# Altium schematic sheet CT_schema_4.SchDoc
size 293 x 258 mm
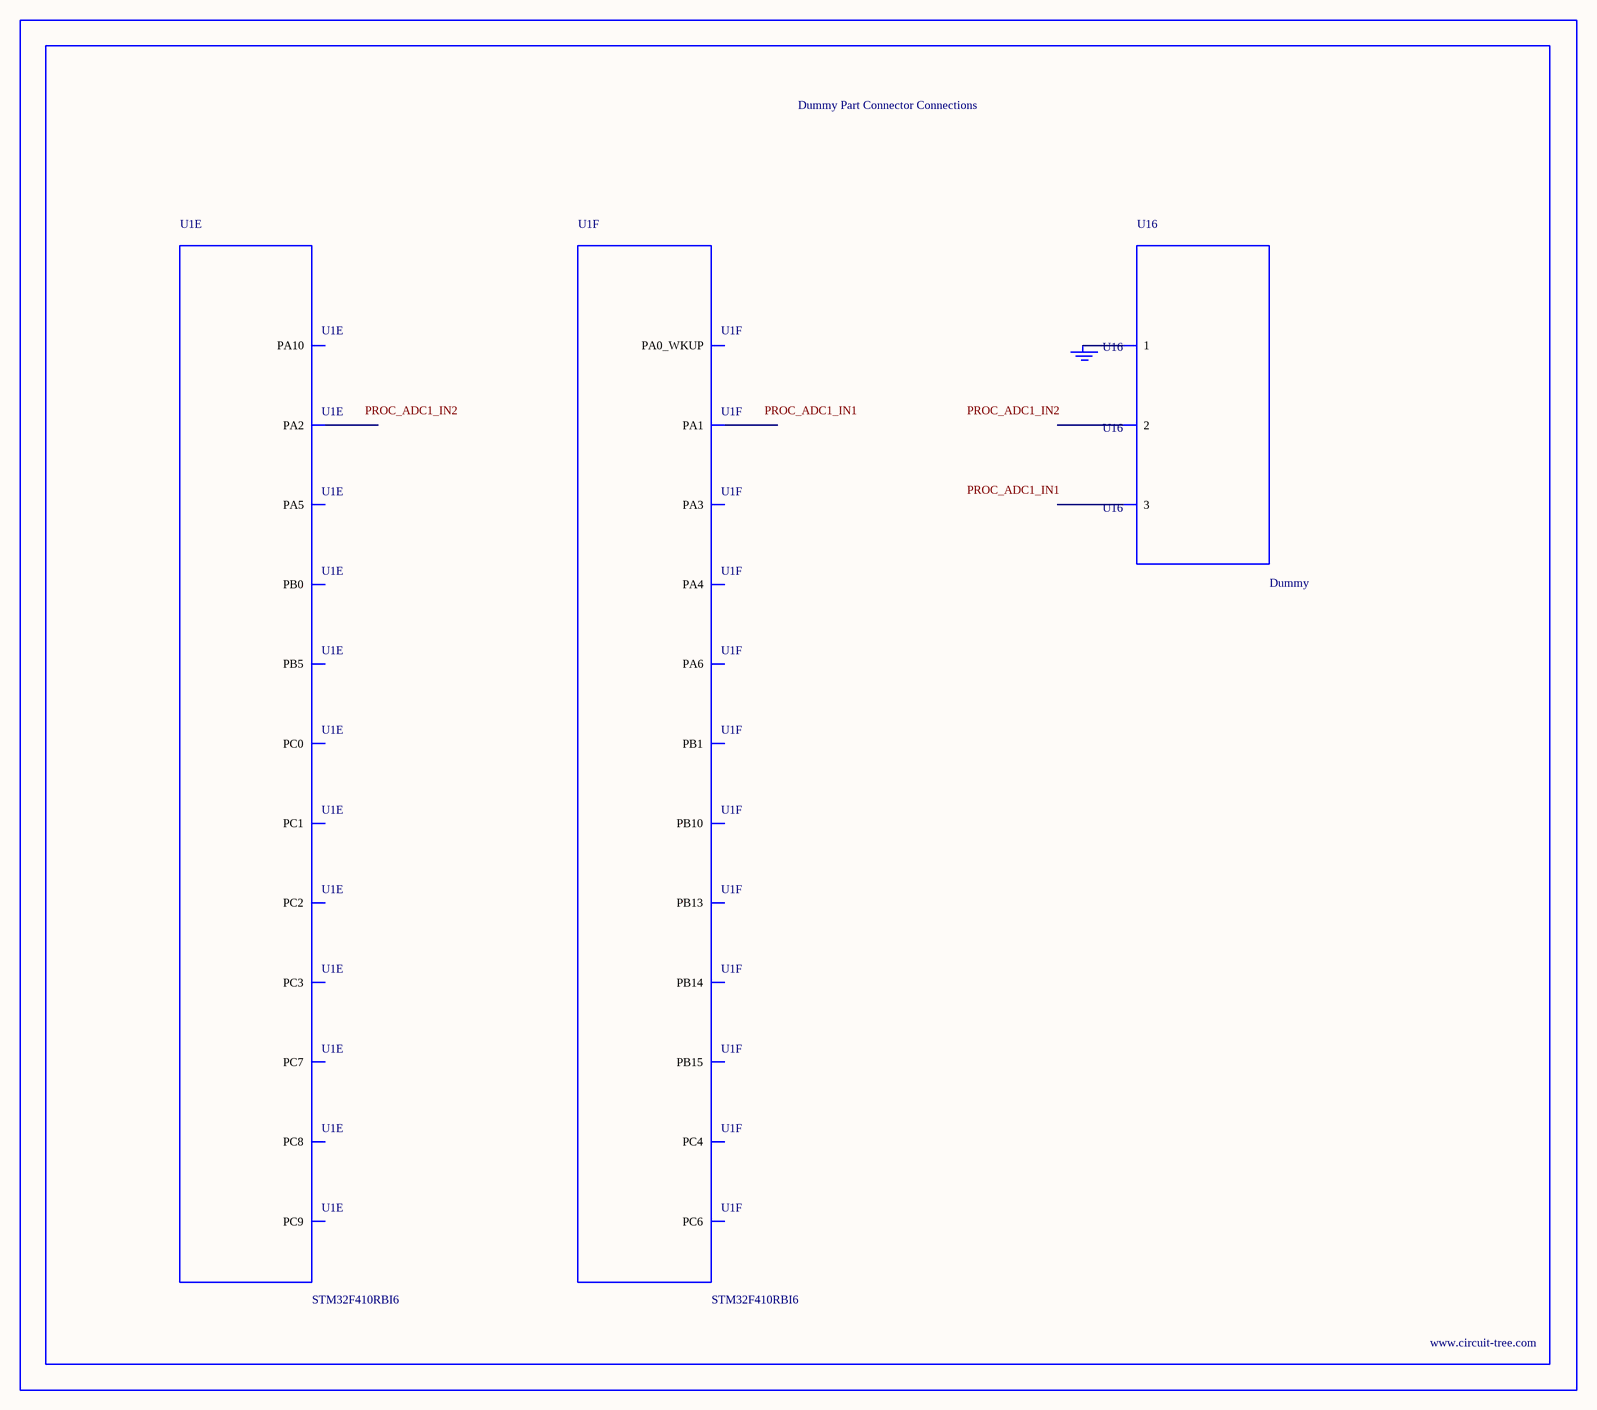
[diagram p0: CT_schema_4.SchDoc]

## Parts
BORDER3  (no value)
GND_INSTANCE_3_0  (no value)
U1  STM32F410RBI6  [UFBGA64]  (parts E,F of 6)
U16  Dummy  [DUMMY_PACKAGE_134]

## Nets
NetGND_INSTANCE_3_0_0: GND_INSTANCE_3_0.0(GND) U16.1

Not connected (* = marked no-connect by the designer): U1 D3(PC0) D4(PB5) D8(PC9) E2(PC1) E3(PC2) E6(PA10) E7(PC7) E8(PC8) F2(PC3) F3(PA2) F4(PA5) F5(PB0) F6(PC6) F7(PB15) F8(PB14) G2(PA0_WKUP) G3(PA3) G4(PA6) G5(PC4) G6(PB1) G7(PB10) G8(PB13) H2(PA1) H3(PA4); U16 2 3

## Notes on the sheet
- Labels drawn without touching a wire or pin: PROC_ADC1_IN1, PROC_ADC1_IN2

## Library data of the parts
BORDER3 = BORDER_PAGE3
GND_INSTANCE_3_0 = GND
